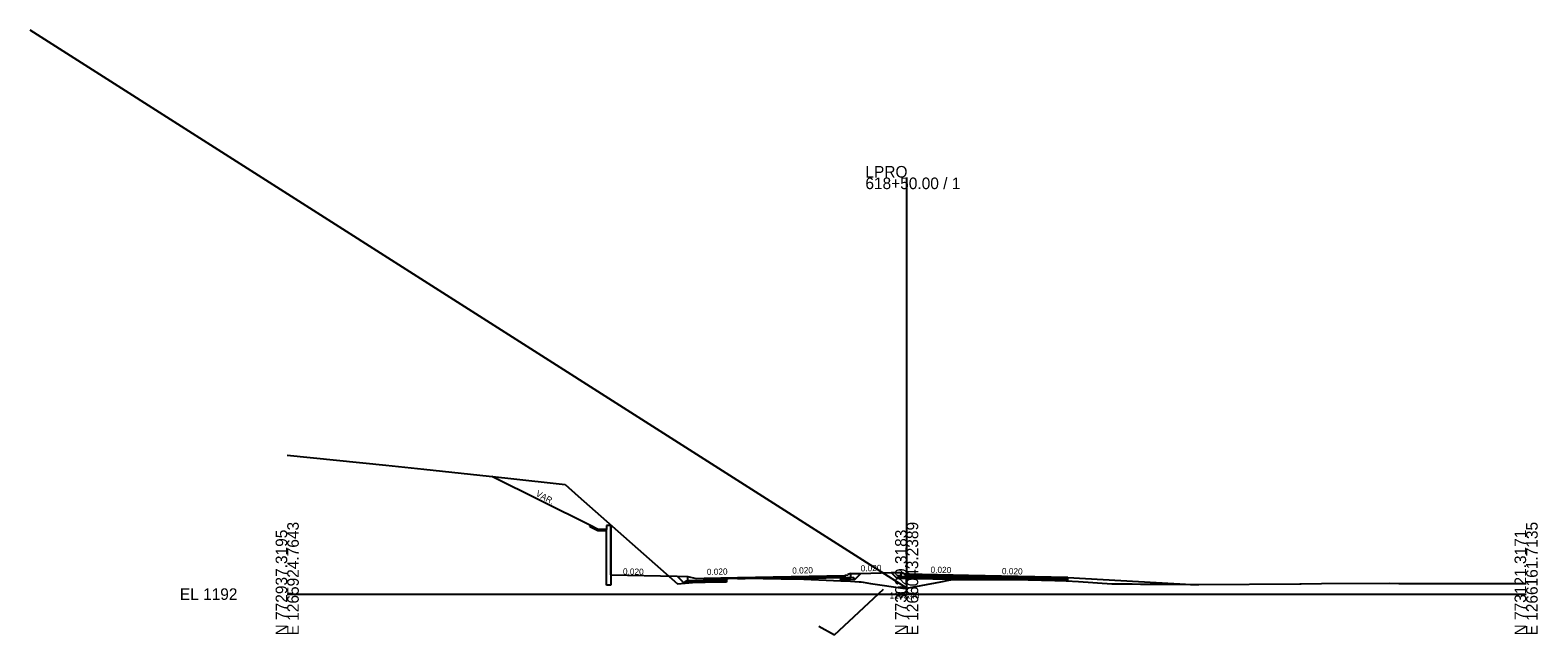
# Model space of a CAD drawing. Extents: x -3833 to 1267678, y -522 to 773248.
# Drawn here: x 1937.8 to 2302.8, y 9490.1 to 9636.5 of the extents above; entities that cross this region are included whole.
import ezdxf

# ---------------------------------------------------------------- set-up
doc = ezdxf.new("R2010")
doc.units = 0
for name, color, linetype in [('Exist Cross Section Cell', 7, 'Continuous'), ('Exist XS Center Line Elevation Label', 7, 'Continuous'), ('Exist XS Ground Line', 7, 'Continuous'), ('Prop CMT DNC', 7, 'Continuous'), ('Prop CMT Pvmt Course 1', 7, 'Continuous'), ('Prop CMT Pvmt Course 2', 7, 'Continuous'), ('Prop CMT Pvmt Course 3', 7, 'Continuous'), ('Prop CMT Pvmt Course 4', 7, 'Continuous'), ('Prop CMT Shld Paved Course 1', 7, 'Continuous'), ('Prop CMT Shld Paved Course 2', 7, 'Continuous'), ('Prop CMT Shld Paved Course 4', 7, 'Continuous'), ('Prop CMT Slope Grass', 7, 'Continuous'), ('Prop CMT Subgrade Earthwork', 7, 'Continuous'), ('Prop Conc Curb and Gutter', 7, 'Continuous'), ('Prop Conc Island Cover', 7, 'Continuous'), ('Prop Corridor Mesh Bottom', 7, 'Continuous'), ('Prop XS Ditch Slope Text', 7, 'Continuous'), ('Prop XS Finish Grade', 7, 'Continuous'), ('Prop XS SE Text', 7, 'Continuous'), ('Scratch_Level_1', 7, 'Continuous'), ('Scratch_Level_5', 7, 'Continuous')]:
    doc.layers.add(name, color=color, linetype=linetype)

msp = doc.modelspace()

# ---------------------------------------------------------------- linework, layer by layer
at = {"layer": 'Exist Cross Section Cell'}
for p, q in [((2150, 9500), (2150, 9600.84)), ((2000, 9500), (2150, 9500)), ((2150, 9500), (2300, 9500))]:
    msp.add_line(p, q, dxfattribs=at)
at = {"layer": 'Exist XS Ground Line'}
for p, q in [((2000, 9533.61), (2023.91, 9531.19)), ((2023.91, 9531.19), (2033.09, 9530.24)), ((2033.09, 9530.24), (2053.46, 9528.1)), ((2053.46, 9528.1), (2067.28, 9526.56)), ((2067.28, 9526.56), (2070.45, 9523.7)), ((2070.45, 9523.7), (2094.48, 9502.47)), ((2100.03, 9502.99), (2106.81, 9503.77)), ((2106.81, 9503.77), (2108.9, 9503.84)), ((2108.9, 9503.84), (2110.88, 9503.88)), ((2110.88, 9503.88), (2119.64, 9503.72)), ((2119.64, 9503.72), (2123.35, 9503.67)), ((2123.35, 9503.67), (2134.07, 9503.25)), ((2134.07, 9503.25), (2136.37, 9503.17)), ((2158.29, 9503), (2160.24, 9503.41)), ((2160.24, 9503.41), (2160.72, 9503.46)), ((2160.72, 9503.46), (2161.24, 9503.52)), ((2161.24, 9503.52), (2162.06, 9503.53)), ((2162.06, 9503.53), (2164.2, 9503.56)), ((2164.2, 9503.56), (2173.26, 9503.58)), ((2173.26, 9503.58), (2176.23, 9503.57)), ((2176.23, 9503.57), (2185.84, 9503.33)), ((2185.84, 9503.33), (2188.63, 9503.25)), ((2188.63, 9503.25), (2191.63, 9503.06)), ((2094.48, 9502.47), (2100.03, 9502.99)), ((2136.37, 9503.17), (2138.51, 9503.01)), ((2138.51, 9503.01), (2138.95, 9502.97)), ((2138.95, 9502.97), (2139.46, 9502.92)), ((2139.46, 9502.92), (2141.24, 9502.61)), ((2141.24, 9502.61), (2149.61, 9501.39)), ((2149.61, 9501.39), (2150, 9501.46)), ((2150, 9501.46), (2158.29, 9503)), ((2191.63, 9503.06), (2199.68, 9502.52)), ((2199.68, 9502.52), (2200.1, 9502.51)), ((2200.1, 9502.51), (2200.49, 9502.5)), ((2200.49, 9502.5), (2201.51, 9502.49)), ((2201.51, 9502.49), (2202.92, 9502.49)), ((2202.92, 9502.49), (2204.59, 9502.47)), ((2204.59, 9502.47), (2206.63, 9502.45)), ((2206.63, 9502.45), (2209.13, 9502.43)), ((2209.13, 9502.43), (2212.13, 9502.41)), ((2212.13, 9502.41), (2218.73, 9502.37)), ((2218.73, 9502.37), (2220.71, 9502.36)), ((2220.71, 9502.36), (2245.23, 9502.51)), ((2245.23, 9502.51), (2245.56, 9502.52)), ((2245.56, 9502.52), (2250.45, 9502.57)), ((2250.45, 9502.57), (2266.94, 9502.63)), ((2266.94, 9502.63), (2269.19, 9502.61)), ((2269.19, 9502.61), (2270.95, 9502.6)), ((2270.95, 9502.6), (2277.85, 9502.59)), ((2277.85, 9502.59), (2281, 9502.59)), ((2281, 9502.59), (2300, 9502.54))]:
    msp.add_line(p, q, dxfattribs=at)
at = {"layer": 'Prop CMT Pvmt Course 1'}
for p, q in [((2109.07, 9504.02), (2135, 9504.54)), ((2135, 9504.29), (2109.07, 9503.77)), ((2109.07, 9503.77), (2109.07, 9504.02)), ((2109.07, 9503.77), (2109.07, 9503.77)), ((2135, 9504.54), (2135, 9504.54)), ((2135, 9504.54), (2135, 9504.29)), ((2135, 9504.29), (2135, 9504.29)), ((2135, 9504.29), (2135, 9504.29)), ((2189, 9504.06), (2165, 9504.54)), ((2165, 9504.54), (2165, 9504.29)), ((2165, 9504.29), (2165, 9504.29)), ((2165, 9504.29), (2189, 9503.81)), ((2189, 9503.81), (2189, 9504.06)), ((2189, 9504.06), (2189, 9504.06)), ((2189, 9504.06), (2219, 9502.36)), ((2189, 9503.81), (2189, 9503.81)), ((2189, 9503.81), (2189, 9503.81))]:
    msp.add_line(p, q, dxfattribs=at)
at = {"layer": 'Prop CMT Pvmt Course 2'}
for p, q in [((2135, 9504.29), (2135, 9504.29)), ((2135, 9504.29), (2135, 9503.96)), ((2135, 9503.96), (2135, 9503.96)), ((2135, 9503.96), (2135, 9503.96)), ((2135, 9503.96), (2135, 9503.96)), ((2165, 9504.29), (2150.08, 9504.59)), ((2150.08, 9504.26), (2165, 9503.96)), ((2165, 9503.96), (2165, 9504.29)), ((2165, 9504.29), (2165, 9504.29)), ((2165, 9503.96), (2165, 9503.96)), ((2165, 9503.96), (2165, 9503.96)), ((2165, 9503.96), (2165, 9503.96))]:
    msp.add_line(p, q, dxfattribs=at)
at = {"layer": 'Prop CMT Pvmt Course 3'}
for p, q in [((2137.01, 9504), (2135, 9503.96)), ((2137.46, 9503.55), (2137.01, 9504)), ((2147.78, 9504.01), (2148.07, 9504.3)), ((2148.07, 9504.3), (2150.08, 9504.26))]:
    msp.add_line(p, q, dxfattribs=at)
at = {"layer": 'Prop CMT Pvmt Course 4'}
for p, q in [((2134, 9504.52), (2134, 9503.26)), ((2137.46, 9503.55), (2134, 9503.48)), ((2135, 9503.96), (2135, 9503.96)), ((2135, 9503.96), (2135, 9503.96)), ((2148.07, 9504.3), (2147.63, 9503.85)), ((2147.63, 9503.85), (2165, 9503.5)), ((2148.57, 9504.29), (2148.07, 9504.3)), ((2165, 9503.96), (2150.08, 9504.26)), ((2165, 9503.5), (2165, 9503.96)), ((2165, 9503.96), (2165, 9503.96)), ((2165, 9503.96), (2165, 9503.96))]:
    msp.add_line(p, q, dxfattribs=at)
at = {"layer": 'Prop CMT Shld Paved Course 1'}
for p, q in [((2101, 9503.86), (2109.07, 9504.02)), ((2101, 9503.61), (2101, 9503.86)), ((2109.07, 9503.77), (2101, 9503.61)), ((2101, 9503.61), (2101, 9503.61)), ((2109.07, 9504.02), (2109.07, 9504.02)), ((2109.07, 9504.02), (2109.07, 9503.77)), ((2109.07, 9503.77), (2109.07, 9503.77)), ((2109.07, 9503.77), (2109.07, 9503.77)), ((2135, 9504.54), (2135, 9504.54)), ((2135, 9504.54), (2135, 9504.29)), ((2135, 9504.29), (2135, 9504.29)), ((2135, 9504.29), (2135, 9504.29)), ((2165, 9504.54), (2150.08, 9504.84)), ((2150.08, 9504.59), (2165, 9504.29)), ((2165, 9504.29), (2165, 9504.54)), ((2165, 9504.54), (2165, 9504.54)), ((2165, 9504.29), (2165, 9504.29)), ((2165, 9504.29), (2165, 9504.29))]:
    msp.add_line(p, q, dxfattribs=at)
at = {"layer": 'Prop CMT Shld Paved Course 2'}
for p, q in [((2101, 9503.61), (2106.39, 9503.72)), ((2101, 9503.28), (2101, 9503.61)), ((2106.39, 9503.39), (2101, 9503.28)), ((2106.39, 9503.72), (2106.39, 9503.39)), ((2109.07, 9503.77), (2110.88, 9503.81)), ((2110.88, 9503.81), (2109.07, 9503.77)), ((2110.88, 9503.81), (2119.64, 9503.99)), ((2112.67, 9503.85), (2110.88, 9503.81)), ((2110.88, 9503.81), (2110.88, 9503.81)), ((2110.88, 9503.81), (2110.88, 9503.81)), ((2119.64, 9503.72), (2112.67, 9503.85)), ((2112.67, 9503.85), (2112.67, 9503.85)), ((2119.64, 9503.99), (2123.35, 9504.06)), ((2119.64, 9503.99), (2119.64, 9503.99)), ((2121.63, 9503.69), (2119.64, 9503.72)), ((2119.64, 9503.72), (2119.64, 9503.72)), ((2123.35, 9503.73), (2121.63, 9503.69)), ((2121.63, 9503.69), (2121.63, 9503.69)), ((2123.35, 9504.06), (2134.07, 9504.27)), ((2123.35, 9504.06), (2123.35, 9504.06)), ((2134.07, 9503.94), (2123.35, 9503.73)), ((2123.35, 9503.73), (2123.35, 9503.73)), ((2134.07, 9504.27), (2135, 9504.29)), ((2134.07, 9504.27), (2134.07, 9504.27)), ((2135, 9503.96), (2134.07, 9503.94)), ((2134.07, 9503.94), (2134.07, 9503.94)), ((2135, 9504.29), (2135, 9504.29)), ((2135, 9504.29), (2135, 9503.96)), ((2135, 9503.96), (2135, 9503.96)), ((2135, 9503.96), (2135, 9503.96)), ((2173.26, 9504.13), (2165, 9504.29)), ((2165, 9504.29), (2165, 9503.96)), ((2165, 9503.96), (2165, 9503.96)), ((2165, 9503.96), (2173.26, 9503.79)), ((2176.23, 9504.07), (2173.26, 9504.13)), ((2173.26, 9504.13), (2173.26, 9504.13)), ((2173.26, 9503.79), (2173.26, 9503.79)), ((2173.26, 9503.79), (2176.23, 9503.74)), ((2185.84, 9503.88), (2176.23, 9504.07)), ((2176.23, 9504.07), (2176.23, 9504.07)), ((2176.23, 9503.74), (2176.23, 9503.74)), ((2176.23, 9503.74), (2185.84, 9503.54)), ((2188.63, 9503.82), (2185.84, 9503.88)), ((2185.84, 9503.88), (2185.84, 9503.88)), ((2185.84, 9503.54), (2185.84, 9503.54)), ((2185.84, 9503.54), (2188.63, 9503.49)), ((2188.63, 9503.82), (2188.63, 9503.82)), ((2189, 9503.81), (2188.63, 9503.82)), ((2188.63, 9503.82), (2188.63, 9503.82)), ((2188.63, 9503.49), (2188.63, 9503.49)), ((2188.63, 9503.49), (2188.63, 9503.49)), ((2188.63, 9503.49), (2189, 9503.48)), ((2189, 9503.23), (2189, 9503.81)), ((2189, 9503.48), (2189, 9503.48))]:
    msp.add_line(p, q, dxfattribs=at)
at = {"layer": 'Prop CMT Shld Paved Course 4'}
for p, q in [((2097, 9503.2), (2106.39, 9503.39)), ((2106.39, 9503.39), (2106.39, 9502.93)), ((2096.03, 9502.72), (2096.5, 9503.19)), ((2106.39, 9502.93), (2096.03, 9502.72)), ((2096.5, 9503.19), (2097, 9503.2))]:
    msp.add_line(p, q, dxfattribs=at)
at = {"layer": 'Prop CMT Slope Grass'}
for p, q in [((2094.42, 9504.34), (2097, 9504.28)), ((2136.51, 9504.97), (2138.94, 9505.03)), ((2146.26, 9505.21), (2148.57, 9505.27))]:
    msp.add_line(p, q, dxfattribs=at)
at = {"layer": 'Prop CMT Subgrade Earthwork'}
for p, q in [((2094.42, 9504.34), (2096.03, 9502.72)), ((2106.39, 9503.72), (2106.39, 9502.93)), ((2137.46, 9503.55), (2134, 9503.48)), ((2134, 9503.26), (2134, 9503.48)), ((2137.46, 9503.55), (2138.94, 9505.03)), ((2147.63, 9503.85), (2146.26, 9505.21)), ((2165, 9503.5), (2147.63, 9503.85)), ((2165, 9503.5), (2165, 9503.56)), ((2106.39, 9502.93), (2096.03, 9502.72))]:
    msp.add_line(p, q, dxfattribs=at)
at = {"layer": 'Prop Conc Curb and Gutter'}
for p, q in [((2073.25, 9516.29), (2073.4, 9516.59)), ((2075.25, 9515.29), (2073.25, 9516.29)), ((2075.33, 9515.62), (2073.4, 9516.59)), ((2077.33, 9515.29), (2075.25, 9515.29)), ((2077.33, 9515.62), (2075.33, 9515.62)), ((2077.32, 9502.2), (2077.33, 9515.62)), ((2078.33, 9516.62), (2077.33, 9516.62)), ((2077.33, 9516.62), (2077.33, 9515.62)), ((2078.33, 9516.62), (2078.33, 9516.62)), ((2078.33, 9516.62), (2078.33, 9516.62)), ((2078.33, 9516.62), (2078.33, 9503.41)), ((2078.33, 9503.41), (2078.33, 9502.2)), ((2097, 9503.2), (2097, 9504.28)), ((2097, 9504.28), (2099, 9503.78)), ((2099, 9503.78), (2101, 9503.86)), ((2099, 9503.78), (2099, 9503.78)), ((2099, 9503.78), (2099, 9503.78)), ((2101, 9503.28), (2099, 9503.24)), ((2101, 9503.86), (2101, 9503.28)), ((2101, 9503.28), (2101, 9503.28)), ((2135.75, 9504.56), (2135, 9504.54)), ((2135, 9504.54), (2135, 9504.54)), ((2135, 9504.54), (2135, 9503.96)), ((2135, 9503.96), (2136.51, 9503.99)), ((2135, 9503.96), (2135, 9503.96)), ((2135, 9503.96), (2135, 9503.96)), ((2136.51, 9504.97), (2135.75, 9504.72)), ((2135.75, 9504.72), (2135.75, 9504.72)), ((2135.75, 9504.72), (2135.75, 9504.56)), ((2135.75, 9504.56), (2135.75, 9504.56)), ((2136.51, 9503.99), (2136.51, 9504.97)), ((2136.51, 9503.99), (2136.51, 9503.99)), ((2149.32, 9505.02), (2148.57, 9505.27)), ((2148.57, 9505.27), (2148.57, 9504.31)), ((2148.57, 9504.31), (2148.57, 9504.29)), ((2148.57, 9504.29), (2150.08, 9504.26)), ((2149.33, 9505.02), (2149.32, 9505.02)), ((2149.33, 9504.86), (2149.33, 9505.02)), ((2150.08, 9504.84), (2149.33, 9504.86)), ((2149.33, 9504.86), (2149.33, 9504.86)), ((2150.08, 9504.26), (2150.08, 9504.84)), ((2150.08, 9504.84), (2150.08, 9504.84)), ((2150.08, 9504.26), (2150.08, 9504.26)), ((2150.08, 9504.26), (2150.08, 9504.26)), ((2078.33, 9502.2), (2077.32, 9502.2)), ((2077.32, 9502.2), (2077.32, 9502.2)), ((2078.33, 9502.2), (2078.33, 9502.2)), ((2099, 9503.24), (2097, 9503.2)), ((2097, 9503.2), (2097, 9503.2)), ((2097, 9503.2), (2097, 9503.2)), ((2099, 9503.24), (2099, 9503.24))]:
    msp.add_line(p, q, dxfattribs=at)
at = {"layer": 'Prop Conc Island Cover'}
for p, q in [((2136.51, 9504.97), (2136.51, 9504.72)), ((2136.51, 9504.97), (2136.51, 9504.97)), ((2136.51, 9504.72), (2136.51, 9504.72)), ((2148.57, 9505.02), (2148.57, 9505.27))]:
    msp.add_line(p, q, dxfattribs=at)
at = {"layer": 'Prop Corridor Mesh Bottom'}
for p, q in [((2109.07, 9504.02), (2109.07, 9503.77)), ((2135, 9504.54), (2135, 9504.29)), ((2165, 9504.54), (2165, 9504.29)), ((2189, 9504.06), (2189, 9503.81))]:
    msp.add_line(p, q, dxfattribs=at)
at = {"layer": 'Prop XS Finish Grade'}
for p, q in [((2073.4, 9516.59), (2049.56, 9528.51)), ((2075.33, 9515.62), (2073.4, 9516.59)), ((2077.33, 9515.62), (2075.33, 9515.62)), ((2078.33, 9516.62), (2077.33, 9516.62)), ((2077.33, 9516.62), (2077.33, 9515.62)), ((2078.33, 9504.66), (2078.33, 9516.62)), ((2078.33, 9504.66), (2094.42, 9504.34)), ((2136.51, 9504.97), (2136.51, 9504.97)), ((2138.94, 9505.03), (2146.26, 9505.21))]:
    msp.add_line(p, q, dxfattribs=at)
at = {"layer": 'Scratch_Level_1'}
msp.add_line((2150, 9501.46), (1937.75, 9636.52), dxfattribs=at)
at = {"layer": 'Scratch_Level_5'}
for p, q in [((2132.55, 9490.14), (2144.41, 9501.17)), ((2128.76, 9492.25), (2132.55, 9490.14))]:
    msp.add_line(p, q, dxfattribs=at)

# ---------------------------------------------------------------- texts
at = {"layer": 'Exist Cross Section Cell'}
for s, p in [('LPRO', (2140, 9600.84)), ('618+50.00 / 1', (2140, 9598.04)), ('EL 1192', (1974, 9498.6))]:
    msp.add_text(s, height=2.8, dxfattribs=at).set_placement(p)
for s, p in [('N 772937.3195', (2000, 9490)), ('E 1265924.7643', (2002.8, 9490)), ('N 773029.3183', (2150, 9490)), ('E 1266043.2389', (2152.8, 9490)), ('N 773121.3171', (2300, 9490)), ('E 1266161.7135', (2302.8, 9490))]:
    msp.add_text(s, height=2.8, rotation=90, dxfattribs=at).set_placement(p)
at = {"layer": 'Exist XS Center Line Elevation Label'}
msp.add_text('1193.46', height=1.5, dxfattribs=at).set_placement((2145.86, 9498.94))
at = {"layer": 'Prop CMT DNC'}
for p in [(2090.62, 9505.88), (2099, 9503.78), (2101, 9503.86), (2101, 9503.86), (2109.07, 9504.02), (2109.07, 9504.02), (2135, 9504.54), (2135, 9504.54), (2135.75, 9504.56), (2149.33, 9504.86), (2150, 9504.84), (2165, 9504.54), (2165, 9504.54), (2189, 9504.06), (2189, 9504.06)]:
    msp.add_text('X', height=0.00025, dxfattribs=at).set_placement(p)
at = {"layer": 'Prop XS Ditch Slope Text'}
msp.add_text('VAR.', height=1.5, rotation=331.3485, dxfattribs=at).set_placement((2060.05, 9523.87))
at = {"layer": 'Prop XS SE Text'}
for rotation, p in [(1.299, (2138.88, 9505.49)), (359.1158, (2081.29, 9504.74)), (1.397, (2101.63, 9504.62)), (1.397, (2122.3, 9504.94)), (358.8542, (2155.77, 9505.17)), (358.8542, (2173.05, 9504.84))]:
    msp.add_text('0.020', height=1.5, rotation=rotation, dxfattribs=at).set_placement(p)

doc.saveas('drawing.dxf')
